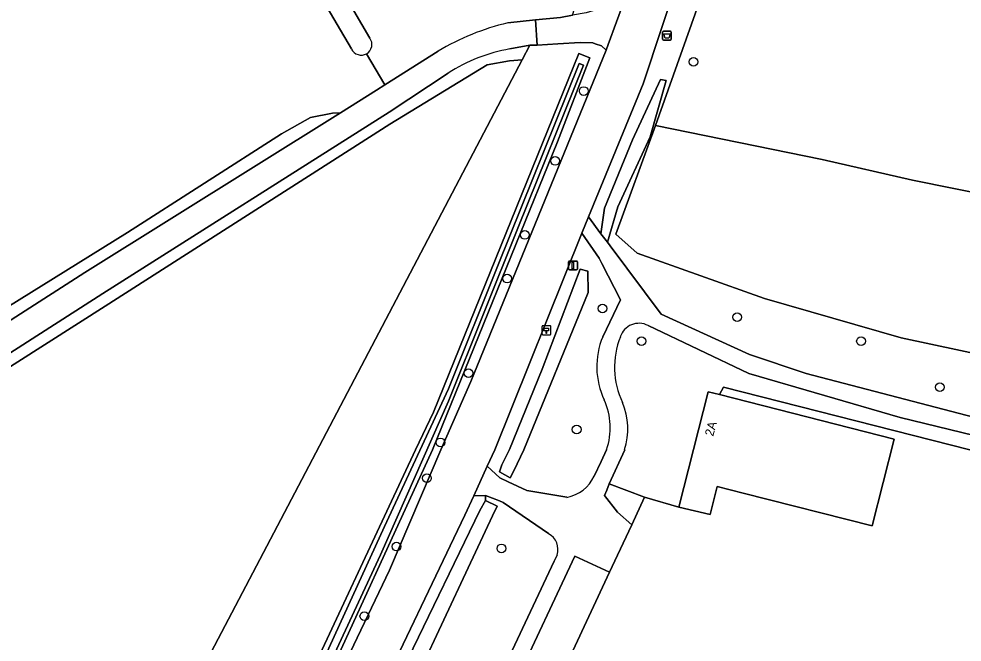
# Model space of a CAD drawing. Extents: x 160203 to 161530, y 379528 to 381797.
# Drawn here: x 160851.3 to 160957.3, y 380978.3 to 381048.5 of the extents above; entities that cross this region are included whole.
import ezdxf

# ---------------------------------------------------------------- set-up
doc = ezdxf.new("R2010")
doc.units = 0
for name, color, linetype in [('IMGEO_Afvalbak', 7, 'Continuous'), ('IMGEO_Berm_groen', 7, 'Continuous'), ('IMGEO_Boom', 7, 'Continuous'), ('IMGEO_Bouwland', 7, 'Continuous'), ('IMGEO_Erf', 7, 'Continuous'), ('IMGEO_Gemengd_bos', 7, 'Continuous'), ('IMGEO_Grasland_agrarisch', 7, 'Continuous'), ('IMGEO_Grasland_overig', 7, 'Continuous'), ('IMGEO_Groenvoorziening', 7, 'Continuous'), ('IMGEO_Hectometerpaal', 7, 'Continuous'), ('IMGEO_Lichtmast', 7, 'Continuous'), ('IMGEO_Loofbos', 7, 'Continuous'), ('IMGEO_Oever', 7, 'Continuous'), ('IMGEO_Pand', 7, 'Continuous'), ('IMGEO_Pand_nummerreeks', 7, 'Continuous'), ('IMGEO_Rijbaan_lokaal_gesloten', 7, 'Continuous'), ('IMGEO_Rijbaan_lokaal_open', 7, 'Continuous'), ('IMGEO_Terreindeel_halfverhard', 7, 'Continuous'), ('IMGEO_Voetpad_halfverhard', 7, 'Continuous'), ('IMGEO_Voetpad_onverhard', 7, 'Continuous'), ('IMGEO_Waterloop', 7, 'Continuous')]:
    doc.layers.add(name, color=color, linetype=linetype)

msp = doc.modelspace()

# ---------------------------------------------------------------- linework, layer by layer
at = {"layer": 'IMGEO_Afvalbak'}
for p, q in [((160923.64, 381046.18), (160923.64, 381046.98)), ((160923.64, 381046.98), (160923.64, 381046.18)), ((160923.74, 381047.08), (160924.53, 381047.08)), ((160924.53, 381047.08), (160923.74, 381047.08)), ((160924.63, 381046.98), (160924.63, 381046.18)), ((160924.63, 381046.18), (160924.63, 381046.98)), ((160924.53, 381046.08), (160923.74, 381046.08)), ((160923.74, 381046.08), (160924.53, 381046.08))]:
    msp.add_line(p, q, dxfattribs=at)
msp.add_lwpolyline([(160923.78, 381046.79), (160924.49, 381046.79), (160924.34, 381046.32), (160923.93, 381046.32), (160923.78, 381046.79)], dxfattribs=at)
for centre, start, end in [((160923.74, 381046.98), 90, 180), ((160923.74, 381046.98), 90, 180), ((160924.53, 381046.98), 0, 90), ((160924.53, 381046.98), 360, 90), ((160923.74, 381046.18), 180, 270), ((160923.74, 381046.18), 180, 270), ((160924.53, 381046.18), 270, 0), ((160924.53, 381046.18), 270, 0)]:
    msp.add_arc(centre, 0.1, start, end, dxfattribs=at)
at = {"layer": 'IMGEO_Berm_groen'}
msp.add_lwpolyline([(160903.11, 380993.15), (160903.75, 380994.27), (160903.74, 380994.85), (160902.43, 380994.82), (160901.43, 380992.62), (160890.8, 380970.43), (160885.68, 380960.32), (160886.73, 380959.43), (160886.96, 380959.86)], close=True, dxfattribs=at)
at = {"layer": 'IMGEO_Boom'}
for centre in [(160927.12, 381043.64), (160914.78, 381040.36), (160911.57, 381032.49), (160908.17, 381024.16), (160906.17, 381019.25), (160916.89, 381015.89), (160932.04, 381014.92), (160921.28, 381012.21), (160945.97, 381012.22), (160901.83, 381008.6), (160954.83, 381007.04), (160913.99, 381002.27), (160898.66, 381000.82), (160897.15, 380996.8), (160893.73, 380989.09), (160905.52, 380988.89), (160890.11, 380981.27)]:
    msp.add_circle(centre, 0.489, dxfattribs=at)
at = {"layer": 'IMGEO_Bouwland'}
for points in [[(160888.65, 381045.09), (160879, 381061.59), (160852.08, 381105.85), (160850.97, 381108.1), (160849.88, 381109.94), (160848.61, 381111.32), (160847.3, 381112.29), (160845.56, 381113.13), (160837.52, 381113.27), (160831.13, 381113), (160822.1, 381112), (160814.34, 381110.81), (160803.73, 381108.67), (160793.94, 381106.94), (160792.38, 381106.63), (160790.8, 381106.18), (160789.06, 381105.36), (160787.65, 381104.43), (160784.19, 381101.79), (160774.24, 381094.27), (160754.42, 381077.5)], [(160909.36, 381048.37), (160912.19, 381048.63), (160913.51, 381048.88), (160929.75, 381100.65), (160917.46, 381102.34), (160887.32, 381106.47), (160852.13, 381110.71), (160854.13, 381107.1), (160881.08, 381062.8), (160890.73, 381046.3)], [(160906.23, 381048.02), (160909.36, 381048.37)], [(160890.36, 381044.56), (160892.41, 381041.05), (160898.41, 381044.84)], [(160887.41, 381037.92), (160891.49, 381040.47), (160892.41, 381041.05), (160890.36, 381044.56)], [(160807.47, 380989.61), (160863.49, 381024.44), (160880.79, 381035.56), (160884.05, 381037.38), (160886.51, 381037.86), (160887.41, 381037.92)]]:
    msp.add_lwpolyline(points, dxfattribs=at)
for centre, radius, start, end in [((160912.57, 381021.21), 27.55, 103.3, 120.9303), ((160889.75, 381045.6), 1.21, 300.4535, 35.8684), ((160889.77, 381045.65), 1.25, 206.775, 298.4634)]:
    msp.add_arc(centre, radius, start, end, dxfattribs=at)
at = {"layer": 'IMGEO_Erf'}
msp.add_lwpolyline([(160992.81, 380974.25), (160992.03, 380991.59), (160958.22, 381000), (160930.49, 381007.05), (160930.04, 381006.19), (160949.7, 381001.19), (160947.21, 380991.42), (160932.71, 380995.11), (160929.8, 380995.85), (160929.01, 380992.69), (160925.47, 380993.53), (160921.61, 380994.65), (160920.18, 380991.56), (160918.58, 380988.13), (160917.68, 380986.21), (160911.25, 380972.39)], dxfattribs=at)
at = {"layer": 'IMGEO_Gemengd_bos'}
msp.add_lwpolyline([(161000, 381024.69), (160986.5, 381025.29), (160972.41, 381026.64), (160966.1, 381027.45), (160951.77, 381030.31), (160941.6, 381032.67), (160922.87, 381036.49), (160918.39, 381024.25), (160920.81, 381022.1), (160935.11, 381017.02), (160950.47, 381012.57), (160986.68, 381004.85), (161000, 381003.3), (161018.8, 381001.64), (161018.47, 381014.06), (161019.82, 381019.66)], close=True, dxfattribs=at)
at = {"layer": 'IMGEO_Grasland_agrarisch'}
msp.add_lwpolyline([(161001.01, 381068.01), (160941.32, 381077.44), (160936.75, 381077.75), (160935.38, 381074.73), (160932.29, 381064.88), (160931.34, 381061.85), (160927.32, 381049.03), (160922.87, 381036.49), (160941.6, 381032.67), (160951.77, 381030.31), (160966.1, 381027.45)], dxfattribs=at)
msp.add_lwpolyline([(160858.7, 380950.21), (160907.85, 381043.87), (160906.45, 381043.75), (160903.91, 381043.31), (160892.97, 381036.64), (160860.97, 381016.14), (160810.15, 380983.79)], close=True, dxfattribs=at)
at = {"layer": 'IMGEO_Grasland_overig'}
for points in [[(160809.54, 380978.38), (160810.13, 380978.79), (160810.15, 380983.79), (160860.97, 381016.14), (160892.97, 381036.64), (160903.91, 381043.31), (160906.45, 381043.75), (160907.85, 381043.87), (160908.71, 381045.51), (160906.49, 381045.09)], [(160899.54, 381042.37), (160892.92, 381037.99), (160860.69, 381017.57), (160833.27, 381000), (160809.42, 380984.71), (160806.62, 380983), (160803.62, 380981.16), (160799.46, 380978.6), (160761.73, 380955.45), (160739.54, 380941.93), (160698.99, 380918.12), (160675.9, 380904.09), (160673.83, 380902.02), (160693.36, 380913.87), (160713.84, 380925.46), (160801.3, 380978.3), (160809.82, 380976.88), (160809.37, 380977.31), (160809.28, 380977.77), (160809.54, 380978.38)], [(160810.22, 380988.86), (160827.59, 381000), (160858.66, 381019.93), (160887.41, 381037.92), (160886.51, 381037.86), (160884.05, 381037.38), (160880.79, 381035.56), (160863.49, 381024.44), (160807.47, 380989.61)]]:
    msp.add_lwpolyline(points, dxfattribs=at)
msp.add_lwpolyline([(160917.12, 380994.86), (160918.57, 380992.96), (160920.18, 380991.56), (160921.61, 380994.65), (160917.64, 380996.15), (160917.39, 380995.43)], close=True, dxfattribs=at)
msp.add_arc((160909.8, 381026.4), 18.99, 100.035, 122.7218, dxfattribs=at)
at = {"layer": 'IMGEO_Groenvoorziening'}
for points in [[(160949.77, 381127.68), (160934.49, 381079.74), (160933.95, 381078.05), (160929.84, 381066.2), (160928.46, 381062.22), (160927.74, 381060.12), (160921.46, 381041.16), (160915.33, 381026.22), (160916.69, 381024.3), (160917.13, 381027.16), (160920.26, 381034.86), (160923.41, 381041.64), (160924.04, 381041.54), (160922.24, 381035.21), (160918.62, 381027.32), (160917.47, 381023.35), (160917.77, 381022.95), (160923.49, 381015.24), (160933.43, 381010.7), (160939.82, 381008.56), (160958.63, 381003.65)], [(160986.68, 381004.85), (160950.47, 381012.57), (160935.11, 381017.02), (160920.81, 381022.1), (160918.39, 381024.25), (160922.87, 381036.49), (160927.32, 381049.03), (160931.34, 381061.85), (160932.29, 381064.88), (160935.38, 381074.73), (160936.75, 381077.75), (160937.19, 381078.73), (160941.43, 381078.44), (161000, 381069.23)]]:
    msp.add_lwpolyline(points, dxfattribs=at)
at = {"layer": 'IMGEO_Hectometerpaal'}
for p, q in [((160910.09, 381013.86), (160910.09, 381013.02)), ((160910.09, 381013.86), (160910.09, 381013.02)), ((160911, 381013.94), (160910.16, 381013.94)), ((160911, 381013.94), (160910.16, 381013.94)), ((160910.17, 381012.94), (160911.01, 381012.94)), ((160910.17, 381012.94), (160911.01, 381012.94)), ((160911.09, 381013.03), (160911.09, 381013.87)), ((160911.09, 381013.03), (160911.09, 381013.87))]:
    msp.add_line(p, q, dxfattribs=at)
msp.add_lwpolyline([(160910.61, 381013.09), (160910.55, 381013.09), (160910.55, 381013.39), (160910.33, 381013.39), (160910.33, 381013.66), (160910.83, 381013.66), (160910.83, 381013.39), (160910.61, 381013.39), (160910.61, 381013.09)], dxfattribs=at)
for centre, start, end in [((160910.17, 381013.87), 92.4484, 184.2845), ((160910.17, 381013.87), 92.4484, 184.2845), ((160910.17, 381013.02), 182.4484, 274.2845), ((160910.17, 381013.02), 182.4484, 274.2845), ((160911.01, 381013.87), 2.4484, 94.2845), ((160911.01, 381013.87), 2.4484, 94.2845), ((160911.01, 381013.02), 272.4484, 4.2845), ((160911.01, 381013.02), 272.4484, 4.2845)]:
    msp.add_arc(centre, 0.0779, start, end, dxfattribs=at)
at = {"layer": 'IMGEO_Lichtmast'}
for p, q in [((160913.08, 381020.33), (160913.08, 381021.13)), ((160913.08, 381021.13), (160913.08, 381020.33)), ((160913.18, 381021.23), (160913.97, 381021.23)), ((160913.97, 381021.23), (160913.18, 381021.23)), ((160914.07, 381021.13), (160914.07, 381020.33)), ((160914.07, 381020.33), (160914.07, 381021.13)), ((160913.97, 381020.23), (160913.18, 381020.23)), ((160913.18, 381020.23), (160913.97, 381020.23))]:
    msp.add_line(p, q, dxfattribs=at)
msp.add_lwpolyline([(160913.5, 381021.11), (160913.65, 381021.11), (160913.65, 381020.36), (160913.5, 381020.36), (160913.5, 381021.11)], dxfattribs=at)
for centre, start, end in [((160913.18, 381021.13), 90, 180), ((160913.18, 381021.13), 90, 180), ((160913.97, 381021.13), 0, 90), ((160913.97, 381021.13), 360, 90), ((160913.18, 381020.33), 180, 270), ((160913.18, 381020.33), 180, 270), ((160913.97, 381020.33), 270, 0), ((160913.97, 381020.33), 270, 0)]:
    msp.add_arc(centre, 0.1, start, end, dxfattribs=at)
at = {"layer": 'IMGEO_Loofbos'}
for points in [[(160892.95, 380986.45), (160898.73, 381000), (160902.08, 381007.67), (160917.29, 381044.96), (160916.77, 381045.43), (160916.08, 381045.68), (160915.79, 381045.79), (160914.37, 381045.83), (160911.89, 381045.66), (160909.56, 381045.52), (160909.26, 381045.52), (160908.71, 381045.51), (160907.85, 381043.87), (160858.7, 380950.21)], [(160849.16, 380917.09), (160865.84, 380942.85), (160873.3, 380954.74), (160881.89, 380970.06), (160895.87, 381000), (160897.9, 381004.22), (160914.24, 381044.58), (160915.48, 381044.08), (160911.82, 381034.66), (160897.77, 381000), (160884.61, 380971.23), (160878.46, 380959.43), (160873.47, 380950.83), (160867.18, 380940.56), (160863.19, 380934.81), (160848.01, 380912.03)], [(160916.92, 381012.7), (160918.92, 381016.87), (160916.83, 381020.95), (160916.53, 381021.54), (160914.57, 381024.37), (160904.79, 381000), (160903.94, 380998.14), (160905.35, 380996.82), (160906.3, 380996.38), (160908.38, 380995.41), (160912.89, 380994.64)], [(160958.68, 381001.59), (160950.37, 381003.61), (160933.35, 381008.59), (160922.02, 381013.96)], [(160919.39, 381000), (160917.64, 380996.15), (160921.61, 380994.65), (160925.47, 380993.53), (160928.79, 381006.51), (160930.04, 381006.19), (160930.49, 381007.05), (160958.22, 381000), (160992.03, 380991.59), (160992.81, 380974.25), (160997.53, 380974.52), (160997.5, 380975.18), (161000, 380975.31), (161002.48, 380975.45), (161003.27, 380975.49), (161002.03, 380993.24)], [(160915.95, 380997.01), (160916.73, 380998.66), (160917.35, 381000)], [(160910.83, 380990.55), (160905.74, 380994.06), (160905.31, 380994.23), (160903.74, 380994.85), (160903.75, 380994.27), (160905.04, 380993.65), (160904.54, 380992.54), (160890.84, 380963.29), (160888.41, 380958.52), (160886.96, 380959.86), (160886.73, 380959.43), (160888.26, 380958.11), (160890.32, 380956.35), (160894.41, 380952.23), (160895.52, 380953.54), (160898.75, 380960.41), (160911.47, 380987.47)], [(160911.47, 380987.47), (160911.78, 380988.14)], [(160854.02, 380918.09), (160871.57, 380945.42), (160874.53, 380950.78), (160877.07, 380954.85), (160883.67, 380967.04), (160892.95, 380986.45)]]:
    msp.add_lwpolyline(points, dxfattribs=at)
msp.add_lwpolyline([(160905.32, 380997.49), (160905.59, 380998.31), (160906.42, 381000.02), (160910.12, 381009.07), (160914.37, 381020.32), (160915.24, 381020.09), (160915.29, 381017.67), (160908.05, 381000), (160906.93, 380997.63), (160906.5, 380996.82)], close=True, dxfattribs=at)
for centre, radius, start, end in [((160920.99, 381012.02), 2.2, 62.1616, 162.0237), ((160924.95, 381009.35), 8.7, 157.3377, 205.5184), ((160927.43, 381009.29), 9.18, 158.2085, 205.6965), ((160910.04, 381002.47), 7.72, 341.3345, 23.9012), ((160912.03, 381002.34), 7.71, 342.3698, 22.6187), ((160912.09, 380998.83), 4.27, 280.7981, 334.8222), ((160909.89, 380988.78), 2, 341.2683, 62.031)]:
    msp.add_arc(centre, radius, start, end, dxfattribs=at)
at = {"layer": 'IMGEO_Oever'}
for points in [[(160848.01, 380912.03), (160863.19, 380934.81), (160867.18, 380940.56), (160873.47, 380950.83), (160878.46, 380959.43), (160884.61, 380971.23), (160897.77, 381000), (160911.82, 381034.66), (160915.48, 381044.08), (160914.24, 381044.58), (160897.9, 381004.22), (160895.87, 381000), (160881.89, 380970.06), (160873.3, 380954.74), (160865.84, 380942.85), (160849.16, 380917.09)], [(160881.66, 380967.92), (160892.36, 380991.35), (160899.59, 381006.84), (160905.15, 381020.79), (160914.28, 381043.46), (160914.74, 381043.28), (160907.45, 381025.11), (160899.59, 381005.44), (160891.91, 380988.16), (160882.32, 380967.5)]]:
    msp.add_lwpolyline(points, dxfattribs=at)
at = {"layer": 'IMGEO_Pand'}
msp.add_lwpolyline([(160949.7, 381001.19), (160930.04, 381006.19), (160928.79, 381006.51), (160925.47, 380993.53), (160929.01, 380992.69), (160929.8, 380995.85), (160932.71, 380995.11), (160947.21, 380991.42)], close=True, dxfattribs=at)
at = {"layer": 'IMGEO_Rijbaan_lokaal_gesloten'}
for points in [[(160956.05, 381163.95), (160940.76, 381116.4), (160940.28, 381114.91), (160930.71, 381083.28), (160930.08, 381081.4), (160925.53, 381067.76), (160919.78, 381051.79), (160919.4, 381050.73), (160917.55, 381045.59), (160917.29, 381044.96), (160902.08, 381007.67), (160898.73, 381000), (160892.95, 380986.45), (160883.67, 380967.04)], [(160890.8, 380970.43), (160901.43, 380992.62), (160902.43, 380994.82), (160903.94, 380998.14), (160904.79, 381000), (160914.57, 381024.37), (160915.33, 381026.22), (160921.46, 381041.16), (160927.74, 381060.12), (160928.46, 381062.22), (160929.84, 381066.2), (160933.95, 381078.05), (160934.49, 381079.74), (160949.77, 381127.68)]]:
    msp.add_lwpolyline(points, dxfattribs=at)
at = {"layer": 'IMGEO_Rijbaan_lokaal_open'}
msp.add_lwpolyline([(160919.4, 381050.73), (160916.47, 381049.6), (160915.81, 381049.39), (160915.05, 381049.16), (160913.51, 381048.88), (160912.19, 381048.63), (160909.36, 381048.37), (160909.56, 381045.52), (160911.89, 381045.66), (160914.37, 381045.83), (160915.79, 381045.79), (160916.08, 381045.68), (160916.77, 381045.43), (160917.29, 381044.96), (160917.55, 381045.59)], close=True, dxfattribs=at)
at = {"layer": 'IMGEO_Terreindeel_halfverhard'}
msp.add_lwpolyline([(160917.68, 380986.21), (160913.8, 380988), (160906.98, 380973.52), (160911.25, 380972.39)], close=True, dxfattribs=at)
at = {"layer": 'IMGEO_Voetpad_halfverhard'}
for points in [[(160958.63, 381003.65), (160939.82, 381008.56), (160933.43, 381010.7), (160923.49, 381015.24), (160917.77, 381022.95), (160917.47, 381023.35), (160916.69, 381024.3), (160915.33, 381026.22), (160914.57, 381024.37), (160916.53, 381021.54), (160916.83, 381020.95), (160918.92, 381016.87), (160916.92, 381012.7)], [(160922.02, 381013.96), (160933.35, 381008.59), (160950.37, 381003.61), (160958.68, 381001.59)], [(160896.73, 380951.77), (160906.98, 380973.52), (160913.8, 380988), (160917.68, 380986.21), (160918.58, 380988.13), (160920.18, 380991.56), (160918.57, 380992.96), (160917.12, 380994.86), (160917.39, 380995.43), (160917.64, 380996.15), (160919.39, 381000)], [(160917.35, 381000), (160916.73, 380998.66), (160915.95, 380997.01)], [(160912.89, 380994.64), (160908.38, 380995.41), (160906.3, 380996.38), (160905.35, 380996.82), (160903.94, 380998.14), (160902.43, 380994.82), (160903.74, 380994.85), (160905.31, 380994.23), (160905.74, 380994.06), (160910.83, 380990.55)], [(160911.78, 380988.14), (160911.47, 380987.47), (160898.75, 380960.41), (160895.52, 380953.54), (160894.41, 380952.23), (160890.32, 380956.35), (160888.26, 380958.11), (160886.73, 380959.43), (160885.68, 380960.32), (160884.85, 380958.68), (160886.26, 380957.43), (160887.58, 380956.27), (160889.99, 380954.13), (160891.24, 380952.81), (160894.49, 380948.42), (160896.64, 380949.71)]]:
    msp.add_lwpolyline(points, dxfattribs=at)
for centre, radius, start, end in [((160920.99, 381012.02), 2.2, 62.1616, 162.0237), ((160924.95, 381009.35), 8.7, 157.3377, 205.5184), ((160927.43, 381009.29), 9.18, 158.2085, 205.6965), ((160910.04, 381002.47), 7.72, 341.3345, 23.9012), ((160912.03, 381002.34), 7.71, 342.3698, 22.6187), ((160912.09, 380998.83), 4.27, 280.7981, 334.8222), ((160909.89, 380988.78), 2, 341.2683, 62.031)]:
    msp.add_arc(centre, radius, start, end, dxfattribs=at)
at = {"layer": 'IMGEO_Voetpad_onverhard'}
for points in [[(160906.49, 381045.09), (160908.71, 381045.51), (160909.26, 381045.52), (160909.56, 381045.52), (160909.36, 381048.37), (160906.23, 381048.02)], [(160898.41, 381044.84), (160892.41, 381041.05), (160891.49, 381040.47), (160887.41, 381037.92), (160858.66, 381019.93), (160827.59, 381000), (160810.22, 380988.86), (160803.37, 380984.63), (160759.69, 380958.12), (160738.5, 380945.39), (160738.16, 380945.18), (160697.46, 380920.51), (160674.23, 380906.45), (160670.53, 380903.94)], [(160833.27, 381000), (160860.69, 381017.57), (160892.92, 381037.99), (160899.54, 381042.37)]]:
    msp.add_lwpolyline(points, dxfattribs=at)
for centre, radius, start, end in [((160912.57, 381021.21), 27.55, 103.3, 120.9303), ((160909.8, 381026.4), 18.99, 100.035, 122.7218)]:
    msp.add_arc(centre, radius, start, end, dxfattribs=at)
at = {"layer": 'IMGEO_Waterloop'}
for points in [[(160826.39, 381116.55), (160832.08, 381115.55), (160837.12, 381114.7), (160843.6, 381113.61), (160845.56, 381113.13), (160847.3, 381112.29), (160848.61, 381111.32), (160849.88, 381109.94), (160850.97, 381108.1), (160852.08, 381105.85), (160879, 381061.59), (160888.65, 381045.09)], [(160890.73, 381046.3), (160881.08, 381062.8), (160854.13, 381107.1), (160852.13, 381110.71), (160851.88, 381111.18)], [(160882.32, 380967.5), (160891.91, 380988.16), (160899.59, 381005.44), (160907.45, 381025.11), (160914.74, 381043.28), (160914.28, 381043.46), (160905.15, 381020.79), (160899.59, 381006.84), (160892.36, 380991.35), (160881.66, 380967.92)]]:
    msp.add_lwpolyline(points, dxfattribs=at)
for points in [[(160917.47, 381023.35), (160918.62, 381027.32), (160922.24, 381035.21), (160924.04, 381041.54), (160923.41, 381041.64), (160920.26, 381034.86), (160917.13, 381027.16), (160916.69, 381024.3)], [(160908.05, 381000), (160915.29, 381017.67), (160915.24, 381020.09), (160914.37, 381020.32), (160910.12, 381009.07), (160906.42, 381000.02), (160905.59, 380998.31), (160905.32, 380997.49), (160906.5, 380996.82), (160906.93, 380997.63)], [(160886.96, 380959.86), (160888.41, 380958.52), (160890.84, 380963.29), (160904.54, 380992.54), (160905.04, 380993.65), (160903.75, 380994.27), (160903.11, 380993.15)]]:
    msp.add_lwpolyline(points, close=True, dxfattribs=at)
for centre, radius, start, end in [((160889.75, 381045.6), 1.21, 300.4535, 35.8684), ((160889.77, 381045.65), 1.25, 206.775, 298.4634)]:
    msp.add_arc(centre, radius, start, end, dxfattribs=at)

# ---------------------------------------------------------------- texts
at = {"layer": 'IMGEO_Pand_nummerreeks'}
msp.add_text('2A', height=1, rotation=74.6392, dxfattribs=at).set_placement((160929.34, 381001.44))

doc.saveas('drawing.dxf')
